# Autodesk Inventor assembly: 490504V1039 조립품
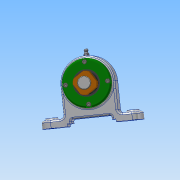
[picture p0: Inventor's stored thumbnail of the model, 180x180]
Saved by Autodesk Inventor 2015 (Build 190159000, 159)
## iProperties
Created: 2019-05
Part Number: 490504V1039 조립품
Document SubType Name: Assembly
Designer: user
Author: user
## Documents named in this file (13)
- C:\Users\user\Desktop\490504V1039 조립품.iam
- C:\Users\user\Desktop\490504V1039\490504V1039 모델링.ipt
- C:\Users\user\Desktop\490504V1039\개스킷.ipt
- C:\Users\user\Desktop\490504V1039\그리스니플 M6.ipt
- 그리스니플  M6.ipt
- C:\Users\user\Desktop\490504V1039\그리스니플개스킷.ipt
- C:\Users\user\Desktop\490504V1039\베어링너트.ipt
- C:\Users\user\Desktop\490504V1039\볼트 M4.ipt
- C:\Users\user\Desktop\490504V1039\앵귤러 볼 베어링 7205.ipt
- C:\Users\user\Desktop\490504V1039\오일 실 28 40 5 B.ipt
- C:\Users\user\Desktop\490504V1039\축.ipt
- C:\Users\user\Desktop\490504V1039\칼라.ipt
- C:\Users\user\Desktop\490504V1039\커버.ipt
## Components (5 placed, 4 different names)
1. 490504V1039 모델링:1
2. 개스킷:1
3. 그리스니플  M6:1
4. 그리스니플개스킷:1
5. 개스킷:2
